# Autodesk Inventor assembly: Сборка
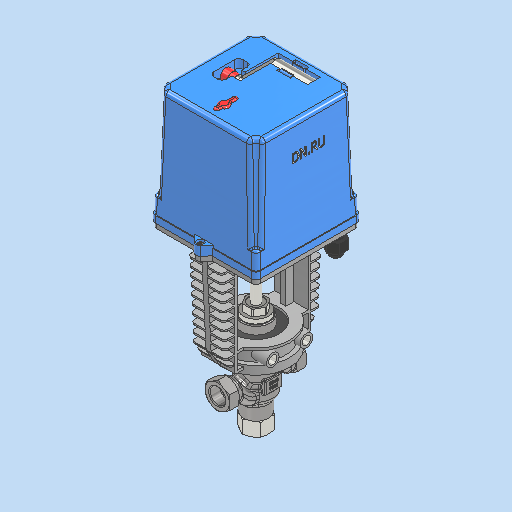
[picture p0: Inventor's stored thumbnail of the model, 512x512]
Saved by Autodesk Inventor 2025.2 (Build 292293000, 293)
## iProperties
Created: 2026-04
Part Number: Сборка
Document SubType Name: Assembly
Designer: igorr
Author: igorr
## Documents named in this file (7)
- D:\PROJECT CAD\DN.RU\...197\DN15\Сборка.iam
- D:\PROJECT CAD\DN.RU\...197\DN15\Деталь 1.ipt
- D:\PROJECT CAD\DN.RU\...197\DN15\Деталь 2.ipt
- D:\PROJECT CAD\DN.RU\...197\DN15\Деталь 3.ipt
- C:\Users\igorr\OneDrive\Документы\Inventor\Content Center Files\R2025\ru-RU\AS 1421(2)\AS 1421 - M10 x 12 засверленный конец.ipt
- C:\Users\igorr\OneDrive\Документы\Inventor\Content Center Files\R2025\ru-RU\AS 1420\AS 1420 - 1973 - M5 x 10.ipt
- C:\Users\igorr\OneDrive\Документы\Inventor\Content Center Files\R2025\ru-RU\AS 1427(05)\AS 1427 - M3 x 8(5) II.ipt
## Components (8 placed, 6 different names)
1. Деталь 1:1 — Касательность:1, Касательность:2, Угол:1, Совмещение:1, Совмещение:5, Угол:3, Заподлицо:1, Совмещение:8, Совмещение:10, Совмещение:11
2. Деталь 2:1 — Касательность:1, Касательность:2, Угол:1, Совмещение:1
3. Деталь 3:1 — Совмещение:2, Совмещение:3, Угол:2, Совмещение:5, Угол:3, Совмещение:11
4. AS 1421 засверленный конец - метрическая M10 x 12 засверленный конец:1 — Заподлицо:1
5. AS 1420 - метрическая M5 x 10:1 — Совмещение:8
6. AS 1420 - метрическая M5 x 10:2 — Совмещение:10
7. AS 1427 H - метрическая M3 x 8:1
8. AS 1427 H - метрическая M3 x 8:2
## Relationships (13: Mate 7, Angle 3, Tangent 2, Flush 1)
- Касательность:1 [Tangent]: Деталь 1:1 ↔ Деталь 2:1
- Касательность:2 [Tangent]: Деталь 1:1 ↔ Деталь 2:1
- Угол:1 [Angle]: Деталь 1:1 ↔ Деталь 2:1
- Совмещение:1 [Mate]: Деталь 1:1 ↔ Деталь 2:1
- Совмещение:2 [Mate]: Деталь 3:1
- Совмещение:3 [Mate]: Деталь 3:1
- Угол:2 [Angle]: Деталь 3:1
- Совмещение:5 [Mate]: Деталь 1:1 ↔ Деталь 3:1
- Угол:3 [Angle]: Деталь 1:1 ↔ Деталь 3:1
- Заподлицо:1 [Flush]: Деталь 1:1 ↔ AS 1421 засверленный конец - метрическая M10 x 12 засверленный конец:1
- Совмещение:8 [Mate]: Деталь 1:1 ↔ AS 1420 - метрическая M5 x 10:1
- Совмещение:10 [Mate]: Деталь 1:1 ↔ AS 1420 - метрическая M5 x 10:2
- Совмещение:11 [Mate]: Деталь 1:1 ↔ Деталь 3:1
